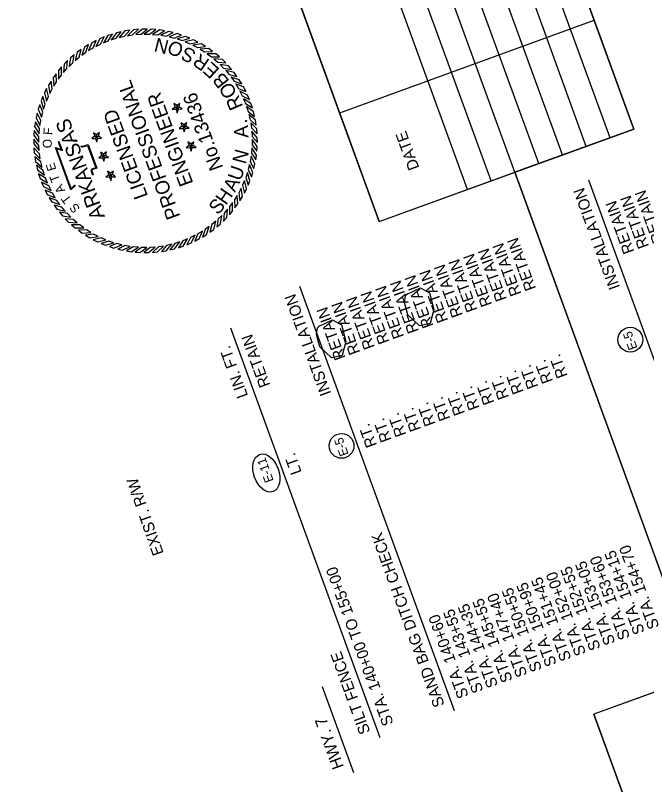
# Model space of a CAD drawing. Extents: x 986289 to 987754, y 1871116 to 1872971.
# Drawn here: x 986700.1 to 987036.8, y 1871784 to 1872194.5 of the extents above; entities that cross this region are included whole.
import ezdxf

# ---------------------------------------------------------------- set-up
doc = ezdxf.new("R2010")
doc.units = 0
for name, color, linetype in [('1', 7, 'Continuous'), ('44', 7, 'Continuous'), ('Default', 7, 'Continuous'), ('G-ANNO-SYMB', 7, 'Continuous'), ('NO PLOT', 7, 'Continuous'), ('R_Draft', 7, 'Continuous'), ('S_TREE', 7, 'Continuous')]:
    doc.layers.add(name, color=color, linetype=linetype)

msp = doc.modelspace()

# ---------------------------------------------------------------- linework, layer by layer
at = {"layer": '1'}
for p, q in [((987064.47, 1871841.86), (986966.59, 1872110.78)), ((987122.5, 1871862.99), (987008.75, 1871821.58)), ((987125.95, 1871499.59), (987008.75, 1871821.58))]:
    msp.add_line(p, q, dxfattribs=at)
for centre in [(987028.16, 1872021.45), (986874.09, 1871964.77)]:
    msp.add_circle(centre, 6.61, dxfattribs=at)
msp.add_ellipse((986833.97, 1871950.31), major_axis=(-3.6, 9.89), ratio=0.638788, dxfattribs=at)
at = {"layer": '44'}
for p, q in [((987088.39, 1871880.02), (987005.96, 1872106.5)), ((986934.32, 1871823.34), (986851.89, 1872049.82)), ((986894.7, 1871808.92), (986815.08, 1872027.68)), ((986880.63, 1871790.3), (986863.92, 1871836.2))]:
    msp.add_line(p, q, dxfattribs=at)
at = {"layer": 'Default'}
for p, q in [((987030.02, 1872133.87), (986884.66, 1872533.24)), ((987017.33, 1872129.25), (986871.97, 1872528.62)), ((987004.65, 1872124.63), (986859.29, 1872524)), ((986991.96, 1872120.02), (986846.6, 1872519.39)), ((986979.27, 1872115.4), (986833.92, 1872514.77)), ((986979.27, 1872115.4), (986833.92, 1872514.77)), ((986966.59, 1872110.78), (986821.23, 1872510.15)), ((986953.9, 1872106.17), (986808.54, 1872505.53)), ((986941.22, 1872101.55), (986795.86, 1872500.92)), ((986894.23, 1872084.45), (986748.87, 1872483.82)), ((986873.09, 1872142.53), (987008.88, 1872191.95)), ((986894.23, 1872084.45), (987030.02, 1872133.87))]:
    msp.add_line(p, q, dxfattribs=at)
at = {"layer": 'G-ANNO-SYMB'}
for points in [[(986756.46, 1872185.78), (986753.97, 1872185.17), (986751.25, 1872181.49), (986753.9, 1872182.32)], [(986761.07, 1872186.63), (986758.54, 1872186.21), (986755.54, 1872182.76), (986758.24, 1872183.37)], [(986765.73, 1872187.11), (986763.17, 1872186.89), (986759.91, 1872183.69), (986762.65, 1872184.09)], [(986770.41, 1872187.22), (986767.85, 1872187.21), (986764.34, 1872184.27), (986767.11, 1872184.45)], [(986775.09, 1872186.97), (986772.53, 1872187.15), (986768.81, 1872184.5), (986771.58, 1872184.46)], [(986779.73, 1872186.35), (986777.2, 1872186.73), (986773.28, 1872184.38), (986776.04, 1872184.13)], [(986784.31, 1872185.36), (986781.81, 1872185.95), (986777.72, 1872183.91), (986780.45, 1872183.44)], [(986788.8, 1872184.03), (986786.36, 1872184.8), (986782.12, 1872183.09), (986784.8, 1872182.41)], [(986743.23, 1872181.13), (986740.95, 1872179.95), (986739.17, 1872175.74), (986741.55, 1872177.16)], [(986747.51, 1872183.03), (986745.15, 1872182.03), (986743.04, 1872177.97), (986745.52, 1872179.2)], [(986751.93, 1872184.58), (986749.5, 1872183.77), (986747.08, 1872179.89), (986749.65, 1872180.92)], [(986793.17, 1872182.34), (986790.79, 1872183.3), (986786.43, 1872181.93), (986789.06, 1872181.04)], [(986797.39, 1872180.31), (986795.1, 1872181.46), (986790.65, 1872180.43), (986793.19, 1872179.34)], [(986739.11, 1872178.9), (986736.93, 1872177.55), (986735.48, 1872173.21), (986737.74, 1872174.81)], [(986801.45, 1872177.96), (986799.25, 1872179.29), (986794.73, 1872178.61), (986797.18, 1872177.33)], [(986805.3, 1872175.3), (986803.22, 1872176.8), (986798.66, 1872176.48), (986801, 1872175)], [(986731.45, 1872173.51), (986729.51, 1872171.83), (986728.76, 1872167.32), (986730.74, 1872169.26)], [(986735.18, 1872176.36), (986733.11, 1872174.84), (986732, 1872170.4), (986734.13, 1872172.17)], [(986808.94, 1872172.35), (986806.98, 1872174), (986802.4, 1872174.04), (986804.63, 1872172.38)], [(986727.97, 1872170.39), (986726.16, 1872168.56), (986725.77, 1872164), (986727.59, 1872166.09)], [(986812.33, 1872169.12), (986810.5, 1872170.92), (986805.95, 1872171.32), (986808.03, 1872169.49)], [(986815.46, 1872165.63), (986813.78, 1872167.57), (986809.27, 1872168.32), (986811.2, 1872166.34)], [(986724.74, 1872166.99), (986723.08, 1872165.03), (986723.04, 1872160.46), (986724.7, 1872162.68)], [(986818.3, 1872161.91), (986816.78, 1872163.97), (986812.34, 1872165.08), (986814.12, 1872162.95)], [(986721.78, 1872163.36), (986720.29, 1872161.27), (986720.61, 1872156.71), (986722.08, 1872159.06)], [(986820.84, 1872157.97), (986819.49, 1872160.15), (986815.15, 1872161.6), (986816.76, 1872159.34)], [(986719.12, 1872159.5), (986717.79, 1872157.31), (986718.47, 1872152.78), (986719.76, 1872155.24)], [(986823.07, 1872153.85), (986821.89, 1872156.13), (986817.68, 1872157.92), (986819.1, 1872155.54)], [(986716.77, 1872155.45), (986715.62, 1872153.16), (986716.65, 1872148.7), (986717.74, 1872151.25)], [(986824.97, 1872149.57), (986823.97, 1872151.93), (986819.92, 1872154.04), (986821.14, 1872151.56)], [(986714.74, 1872151.23), (986713.78, 1872148.85), (986715.15, 1872144.49), (986716.04, 1872147.12)], [(986826.52, 1872145.15), (986825.72, 1872147.58), (986821.84, 1872150.01), (986822.87, 1872147.43)], [(986713.06, 1872146.86), (986712.28, 1872144.41), (986713.99, 1872140.17), (986714.67, 1872142.86)], [(986786.39, 1872145.32), (986785.38, 1872145.61), (986783.82, 1872144.39), (986785.8, 1872144.46)], [(986786.39, 1872145.32), (986786.35, 1872146.36), (986784.71, 1872147.47), (986785.38, 1872145.61)], [(986786.39, 1872145.32), (986785.8, 1872144.46), (986786.48, 1872142.59), (986787.03, 1872144.5)], [(986786.39, 1872145.32), (986787.36, 1872145.68), (986787.91, 1872147.58), (986786.35, 1872146.36)], [(986786.39, 1872145.32), (986787.03, 1872144.5), (986789.01, 1872144.57), (986787.36, 1872145.68)], [(986827.73, 1872140.62), (986827.11, 1872143.11), (986823.44, 1872145.83), (986824.26, 1872143.19)], [(986711.72, 1872142.37), (986711.14, 1872139.87), (986713.18, 1872135.78), (986713.64, 1872138.51)], [(986828.57, 1872136.01), (986828.15, 1872138.55), (986824.7, 1872141.55), (986825.32, 1872138.84)], [(986710.74, 1872137.79), (986710.35, 1872135.25), (986712.71, 1872131.33), (986712.96, 1872134.09)], [(986790.12, 1872135.07), (986790.08, 1872136.11), (986788.44, 1872137.22), (986789.11, 1872135.36)], [(986790.12, 1872135.07), (986791.1, 1872135.42), (986791.64, 1872137.33), (986790.08, 1872136.11)], [(986829.05, 1872131.35), (986828.83, 1872133.91), (986825.63, 1872137.17), (986826.03, 1872134.43)], [(986710.11, 1872133.14), (986709.93, 1872130.59), (986712.59, 1872126.86), (986712.62, 1872129.63)], [(986743.46, 1872129.7), (986743.42, 1872130.74), (986741.78, 1872131.84), (986742.46, 1872129.98)], [(986743.46, 1872129.7), (986744.44, 1872130.05), (986744.98, 1872131.96), (986743.42, 1872130.74)], [(986790.12, 1872135.07), (986789.11, 1872135.36), (986787.55, 1872134.14), (986789.53, 1872134.2)], [(986790.12, 1872135.07), (986789.53, 1872134.2), (986790.21, 1872132.34), (986790.76, 1872134.25)], [(986790.12, 1872135.07), (986790.76, 1872134.25), (986792.74, 1872134.32), (986791.1, 1872135.42)], [(986829.17, 1872126.67), (986829.15, 1872129.24), (986826.21, 1872132.74), (986826.39, 1872129.97)], [(986709.86, 1872128.47), (986709.88, 1872125.9), (986712.82, 1872122.4), (986712.63, 1872125.16)], [(986743.46, 1872129.7), (986742.46, 1872129.98), (986740.9, 1872128.76), (986742.88, 1872128.83)], [(986743.46, 1872129.7), (986742.88, 1872128.83), (986743.55, 1872126.97), (986744.1, 1872128.87)], [(986743.46, 1872129.7), (986744.1, 1872128.87), (986746.08, 1872128.94), (986744.44, 1872130.05)], [(986828.91, 1872121.99), (986829.1, 1872124.55), (986826.44, 1872128.28), (986826.41, 1872125.5)], [(986709.97, 1872123.78), (986710.19, 1872121.23), (986713.4, 1872117.97), (986713, 1872120.71)], [(986793.85, 1872124.82), (986792.85, 1872125.1), (986791.28, 1872123.88), (986793.26, 1872123.95)], [(986793.85, 1872124.82), (986793.81, 1872125.86), (986792.17, 1872126.97), (986792.85, 1872125.1)], [(986793.85, 1872124.82), (986793.26, 1872123.95), (986793.94, 1872122.09), (986794.49, 1872124)], [(986793.85, 1872124.82), (986794.83, 1872125.17), (986795.37, 1872127.08), (986793.81, 1872125.86)], [(986793.85, 1872124.82), (986794.49, 1872124), (986796.47, 1872124.07), (986794.83, 1872125.17)], [(986828.29, 1872117.35), (986828.68, 1872119.89), (986826.32, 1872123.81), (986826.07, 1872121.05)], [(986710.45, 1872119.12), (986710.87, 1872116.59), (986714.32, 1872113.59), (986713.71, 1872116.3)], [(986747.19, 1872119.44), (986746.19, 1872119.73), (986744.63, 1872118.51), (986746.61, 1872118.58)], [(986747.19, 1872119.44), (986747.15, 1872120.49), (986745.51, 1872121.59), (986746.19, 1872119.73)], [(986747.19, 1872119.44), (986746.61, 1872118.58), (986747.28, 1872116.72), (986747.83, 1872118.62)], [(986747.19, 1872119.44), (986748.17, 1872119.8), (986748.71, 1872121.71), (986747.15, 1872120.49)], [(986747.19, 1872119.44), (986747.83, 1872118.62), (986749.81, 1872118.69), (986748.17, 1872119.8)], [(986827.31, 1872112.77), (986827.89, 1872115.27), (986825.85, 1872119.36), (986825.38, 1872116.63)], [(986825.97, 1872108.28), (986826.75, 1872110.73), (986825.03, 1872114.97), (986824.35, 1872112.28)], [(986711.3, 1872114.52), (986711.91, 1872112.03), (986715.59, 1872109.31), (986714.76, 1872111.95)], [(986750.92, 1872109.19), (986750.88, 1872110.23), (986749.24, 1872111.34), (986749.92, 1872109.48)], [(986750.92, 1872109.19), (986751.9, 1872109.55), (986752.45, 1872111.45), (986750.88, 1872110.23)], [(986712.5, 1872109.99), (986713.31, 1872107.55), (986717.19, 1872105.13), (986716.16, 1872107.7)], [(986750.92, 1872109.19), (986749.92, 1872109.48), (986748.36, 1872108.26), (986750.34, 1872108.33)], [(986750.92, 1872109.19), (986750.34, 1872108.33), (986751.02, 1872106.47), (986751.56, 1872108.37)], [(986750.92, 1872109.19), (986751.56, 1872108.37), (986753.54, 1872108.44), (986751.9, 1872109.55)], [(986824.28, 1872103.91), (986825.25, 1872106.29), (986823.87, 1872110.65), (986822.98, 1872108.02)], [(986714.06, 1872105.57), (986715.05, 1872103.21), (986719.11, 1872101.1), (986717.88, 1872103.58)], [(986822.26, 1872099.69), (986823.41, 1872101.98), (986822.38, 1872106.44), (986821.29, 1872103.89)], [(986715.95, 1872101.29), (986717.13, 1872099.01), (986721.34, 1872097.22), (986719.92, 1872099.6)], [(986819.91, 1872095.64), (986821.23, 1872097.83), (986820.56, 1872102.35), (986819.27, 1872099.9)], [(986718.18, 1872097.17), (986719.54, 1872094.99), (986723.87, 1872093.54), (986722.27, 1872095.8)], [(986814.29, 1872088.15), (986815.94, 1872090.11), (986815.98, 1872094.68), (986814.33, 1872092.46)], [(986817.25, 1872091.78), (986818.74, 1872093.87), (986818.42, 1872098.43), (986816.94, 1872096.08)], [(986720.73, 1872093.23), (986722.25, 1872091.17), (986726.68, 1872090.06), (986724.91, 1872092.19)], [(986811.06, 1872084.75), (986812.86, 1872086.58), (986813.26, 1872091.13), (986811.43, 1872089.05)], [(986723.57, 1872089.51), (986725.25, 1872087.57), (986729.76, 1872086.82), (986727.82, 1872088.8)], [(986807.57, 1872081.63), (986809.51, 1872083.3), (986810.27, 1872087.81), (986808.28, 1872085.88)], [(986726.7, 1872086.02), (986728.52, 1872084.22), (986733.08, 1872083.82), (986730.99, 1872085.65)], [(986730.09, 1872082.79), (986732.05, 1872081.14), (986736.62, 1872081.1), (986734.4, 1872082.75)], [(986803.85, 1872078.78), (986805.92, 1872080.3), (986807.02, 1872084.74), (986804.89, 1872082.97)], [(986733.72, 1872079.84), (986735.81, 1872078.34), (986740.37, 1872078.66), (986738.02, 1872080.14)], [(986795.79, 1872074.01), (986798.07, 1872075.19), (986799.86, 1872079.4), (986797.48, 1872077.98)], [(986799.92, 1872076.24), (986802.09, 1872077.59), (986803.55, 1872081.93), (986801.28, 1872080.33)], [(986737.58, 1872077.18), (986739.78, 1872075.85), (986744.3, 1872076.53), (986741.84, 1872077.81)], [(986741.63, 1872074.83), (986743.92, 1872073.68), (986748.38, 1872074.7), (986745.83, 1872075.8)], [(986745.86, 1872072.8), (986748.23, 1872071.83), (986752.59, 1872073.21), (986749.97, 1872074.1)], [(986787.09, 1872070.56), (986789.53, 1872071.37), (986791.95, 1872075.25), (986789.38, 1872074.22)], [(986791.51, 1872072.11), (986793.88, 1872073.11), (986795.99, 1872077.17), (986793.5, 1872075.94)], [(986750.23, 1872071.11), (986752.67, 1872070.34), (986756.91, 1872072.05), (986754.22, 1872072.73)], [(986754.71, 1872069.77), (986757.21, 1872069.19), (986761.31, 1872071.23), (986758.57, 1872071.7)], [(986759.29, 1872068.79), (986761.83, 1872068.41), (986765.75, 1872070.76), (986762.99, 1872071.01)], [(986763.94, 1872068.17), (986766.5, 1872067.99), (986770.22, 1872070.64), (986767.45, 1872070.67)], [(986768.62, 1872067.92), (986771.18, 1872067.93), (986774.68, 1872070.87), (986771.92, 1872070.69)], [(986773.3, 1872068.03), (986775.85, 1872068.25), (986779.12, 1872071.45), (986776.37, 1872071.05)], [(986777.96, 1872068.51), (986780.49, 1872068.93), (986783.49, 1872072.38), (986780.79, 1872071.76)], [(986782.57, 1872069.36), (986785.06, 1872069.97), (986787.78, 1872073.65), (986785.13, 1872072.82)]]:
    msp.add_lwpolyline(points, close=True, dxfattribs=at)
for points in [[(986731.82, 1872104.05), (986729.89, 1872102.13), (986722.12, 1872123.44), (986725.2, 1872122.41), (986724.33, 1872124.69), (986723.86, 1872125.94), (986723.54, 1872127.25)], [(986732.09, 1872103.78), (986729.74, 1872101.44), (986721.5, 1872124.05), (986724.56, 1872123.02), (986723.98, 1872124.55), (986723.49, 1872125.83), (986723.17, 1872127.16)], [(986734.92, 1872124.64), (986735.48, 1872124.31), (986736.14, 1872124.36), (986737.41, 1872124.67), (986738.64, 1872125.12), (986742.97, 1872113.21), (986741.22, 1872112.58), (986740.48, 1872112.31), (986740.53, 1872111.4), (986741.13, 1872109.75), (986740.89, 1872109.41)], [(986735.11, 1872124.97), (986735.57, 1872124.7), (986736.08, 1872124.74), (986737.3, 1872125.04), (986738.86, 1872125.61), (986743.46, 1872112.99), (986741.35, 1872112.22), (986740.88, 1872112.05), (986740.91, 1872111.48), (986741.56, 1872109.68), (986741.19, 1872109.19)]]:
    msp.add_lwpolyline(points, dxfattribs=at)
at = {"layer": 'NO PLOT'}
for points in [[(987753.66, 1871472.09), (987208.01, 1872971.24), (986718.28, 1872792.99), (986821.23, 1872510.15), (986884.66, 1872533.24), (987030.02, 1872133.87), (986966.59, 1872110.78), (987064.47, 1871841.86), (987122.5, 1871862.99), (987239.7, 1871540.99), (987181.66, 1871519.87), (987263.93, 1871293.85)], [(987753.66, 1871472.09), (987208.01, 1872971.24), (986718.28, 1872792.99), (986821.23, 1872510.15), (986884.66, 1872533.24), (987030.02, 1872133.87), (986966.59, 1872110.78), (987064.47, 1871841.86), (987122.5, 1871862.99), (987239.7, 1871540.99), (987181.66, 1871519.87), (987263.93, 1871293.85)], [(987753.66, 1871472.09), (987208.01, 1872971.24), (986718.28, 1872792.99), (986821.23, 1872510.15), (986884.66, 1872533.24), (987030.02, 1872133.87), (986966.59, 1872110.78), (987064.47, 1871841.86), (987122.5, 1871862.99), (987239.7, 1871540.99), (987181.66, 1871519.87), (987263.93, 1871293.85)], [(987753.66, 1871472.09), (987208.01, 1872971.24), (986718.28, 1872792.99), (986821.23, 1872510.15), (986884.66, 1872533.24), (987030.02, 1872133.87), (986966.59, 1872110.78), (987064.47, 1871841.86), (987122.5, 1871862.99), (987239.7, 1871540.99), (987181.66, 1871519.87), (987263.93, 1871293.85)], [(987753.66, 1871472.09), (987208.01, 1872971.24), (986718.28, 1872792.99), (986821.23, 1872510.15), (986884.66, 1872533.24), (987030.02, 1872133.87), (986966.59, 1872110.78), (987064.47, 1871841.86), (987122.5, 1871862.99), (987239.7, 1871540.99), (987181.66, 1871519.87), (987263.93, 1871293.85)], [(987753.66, 1871472.09), (987208.01, 1872971.24), (986718.28, 1872792.99), (986821.23, 1872510.15), (986884.66, 1872533.24), (987030.02, 1872133.87), (986966.59, 1872110.78), (987064.47, 1871841.86), (987122.5, 1871862.99), (987239.7, 1871540.99), (987181.66, 1871519.87), (987263.93, 1871293.85)], [(987753.66, 1871472.09), (987208.01, 1872971.24), (986718.28, 1872792.99), (986821.23, 1872510.15), (986884.66, 1872533.24), (987030.02, 1872133.87), (986966.59, 1872110.78), (987064.47, 1871841.86), (987122.5, 1871862.99), (987239.7, 1871540.99), (987181.66, 1871519.87), (987263.93, 1871293.85)], [(986774.2, 1871115.6), (986369.23, 1872228.25), (986415.65, 1872245.15), (986348.68, 1872429.14), (986362.4, 1872434.13), (986288.69, 1872636.64), (986718.28, 1872792.99), (986821.23, 1872510.15), (986748.87, 1872483.82), (986894.23, 1872084.45), (986966.59, 1872110.78), (987064.47, 1871841.86), (987008.75, 1871821.58), (987125.95, 1871499.59), (987181.66, 1871519.87), (987263.93, 1871293.85)], [(986774.2, 1871115.6), (986369.23, 1872228.25), (986415.65, 1872245.15), (986348.68, 1872429.14), (986362.4, 1872434.13), (986288.69, 1872636.64), (986718.28, 1872792.99), (986821.23, 1872510.15), (986748.87, 1872483.82), (986894.23, 1872084.45), (986966.59, 1872110.78), (987064.47, 1871841.86), (987008.75, 1871821.58), (987125.95, 1871499.59), (987181.66, 1871519.87), (987263.93, 1871293.85)], [(986774.2, 1871115.6), (986369.23, 1872228.25), (986415.65, 1872245.15), (986348.68, 1872429.14), (986362.4, 1872434.13), (986288.69, 1872636.64), (986718.28, 1872792.99), (986821.23, 1872510.15), (986748.87, 1872483.82), (986894.23, 1872084.45), (986966.59, 1872110.78), (987064.47, 1871841.86), (987008.75, 1871821.58), (987125.95, 1871499.59), (987181.66, 1871519.87), (987263.93, 1871293.85)], [(986774.2, 1871115.6), (986369.23, 1872228.25), (986415.65, 1872245.15), (986348.68, 1872429.14), (986362.4, 1872434.13), (986288.69, 1872636.64), (986718.28, 1872792.99), (986821.23, 1872510.15), (986748.87, 1872483.82), (986894.23, 1872084.45), (986966.59, 1872110.78), (987064.47, 1871841.86), (987008.75, 1871821.58), (987125.95, 1871499.59), (987181.66, 1871519.87), (987263.93, 1871293.85)], [(986774.2, 1871115.6), (986369.23, 1872228.25), (986415.65, 1872245.15), (986348.68, 1872429.14), (986362.4, 1872434.13), (986288.69, 1872636.64), (986718.28, 1872792.99), (986821.23, 1872510.15), (986748.87, 1872483.82), (986894.23, 1872084.45), (986966.59, 1872110.78), (987064.47, 1871841.86), (987008.75, 1871821.58), (987125.95, 1871499.59), (987181.66, 1871519.87), (987263.93, 1871293.85)], [(986774.2, 1871115.6), (986369.23, 1872228.25), (986415.65, 1872245.15), (986348.68, 1872429.14), (986362.4, 1872434.13), (986288.69, 1872636.64), (986718.28, 1872792.99), (986821.23, 1872510.15), (986748.87, 1872483.82), (986894.23, 1872084.45), (986966.59, 1872110.78), (987064.47, 1871841.86), (987008.75, 1871821.58), (987125.95, 1871499.59), (987181.66, 1871519.87), (987263.93, 1871293.85)]]:
    msp.add_lwpolyline(points, close=True, dxfattribs=at)
at = {"layer": 'S_TREE'}
for points in [[(986908.79, 1872045.63), (986916.26, 1872049.12), (986921.09, 1872046.38), (986923.24, 1872037.55), (986921.31, 1872030.17), (986915.6, 1872028.9), (986909.52, 1872034.78), (986907.67, 1872041.23), (986908.28, 1872044.88), (986909.47, 1872046.1)], [(986861.85, 1872028.54), (986869.32, 1872032.03), (986874.15, 1872029.3), (986876.3, 1872020.47), (986874.37, 1872013.09), (986868.66, 1872011.81), (986862.58, 1872017.7), (986860.73, 1872024.14), (986861.34, 1872027.8), (986862.53, 1872029.02)]]:
    msp.add_lwpolyline(points, dxfattribs=at)

# ---------------------------------------------------------------- texts
at = {"layer": '1'}
for s, p in [('E-5 ', (987032, 1872017)), ('E-5 ', (986877.93, 1871960.32)), ('E-11', (986837.96, 1871946.23))]:
    msp.add_text(s, height=4.8, rotation=110, dxfattribs=at).set_placement(p)
at = {"layer": '44'}
for s, height, p in [('INSTALLATION', 6, (987022.74, 1872049.43)), ('RETAIN', 6, (987046.02, 1872074.2)), ('RETAIN', 6, (987030.36, 1872068.5)), ('RETAIN', 6, (987038.19, 1872071.35)), ('RETAIN', 6, (986977.96, 1872048.83)), ('RETAIN', 6, (986962.34, 1872043.14)), ('RETAIN', 6, (986970.13, 1872045.98)), ('RETAIN', 6, (986954.51, 1872040.29)), ('RETAIN', 6, (986938.89, 1872034.6)), ('RETAIN', 6, (986946.68, 1872037.44)), ('RETAIN', 6, (986931.06, 1872031.75)), ('RETAIN', 6, (986923.2, 1872028.89)), ('RETAIN', 6, (986907.57, 1872023.21)), ('RETAIN', 6, (986915.4, 1872026.06)), ('INSTALLATION', 6, (986868.67, 1871992.75)), ('RETAIN', 6, (986899.74, 1872020.36)), ('RETAIN', 6, (986884.12, 1872014.67)), ('RETAIN', 6, (986891.95, 1872017.52)), ('RETAIN', 6, (986876.29, 1872011.82)), ('RETAIN', 6, (986836.2, 1871997.23)), ('LIN. FT.', 6, (986824.26, 1871991.5)), ('RT.', 6, (986994.81, 1872002.18)), ('RT.', 6, (986986.98, 1871999.33)), ('RT.', 6, (986971.32, 1871993.63)), ('RT.', 6, (986979.15, 1871996.48)), ('RT.', 6, (986963.49, 1871990.78)), ('RT.', 6, (986947.87, 1871985.1)), ('RT.', 6, (986955.7, 1871987.95)), ('RT.', 6, (986940.04, 1871982.25)), ('RT.', 6, (986924.38, 1871976.55)), ('RT.', 6, (986932.21, 1871979.4)), ('RT.', 6, (986916.55, 1871973.7)), ('RT.', 6, (986908.76, 1871970.86)), ('RT.', 6, (986893.1, 1871965.16)), ('RT.', 6, (986900.93, 1871968.01)), ('LT.', 6, (986852.95, 1871950.7)), ('SAND BAG DITCH CHECK', 6, (986929.15, 1871826.56)), ('STA. 154+70', 6, (987043.71, 1871868.26)), ('STA. 153+60', 6, (987028.05, 1871862.56)), ('STA. 154+15', 6, (987035.88, 1871865.41)), ('STA. 153+05', 6, (987020.22, 1871859.71)), ('STA. 140+00 TO 155+00', 6, (986901.9, 1871816.65)), ('STA. 152+00', 6, (987004.6, 1871854.02)), ('STA. 152+55', 6, (987012.39, 1871856.86)), ('STA. 151+45', 6, (986996.77, 1871851.17)), ('STA. 150+95', 6, (986988.94, 1871848.32)), ('STA. 147+40', 6, (986973.28, 1871842.63)), ('STA. 150+55', 6, (986981.11, 1871845.48)), ('STA. 145+55', 6, (986965.45, 1871839.78)), ('STA. 143+55', 6, (986949.83, 1871834.09)), ('STA. 144+35', 6, (986957.66, 1871836.94)), ('STA. 140+60', 6, (986942, 1871831.24)), ('SILT FENCE      ', 6, (986889.53, 1871812.14)), ('HWY. 7', 6.25, (986875.42, 1871793.56))]:
    msp.add_text(s, height=height, rotation=110, dxfattribs=at).set_placement(p)
at = {"layer": 'Default'}
msp.add_text('DATE', height=6, rotation=110, dxfattribs=at).set_placement((986915.7, 1872113.17))
at = {"layer": 'G-ANNO-SYMB'}
for s, height, rotation, p in [('N', 7.5, 166.1007, (986782.47, 1872180.96)), ('O', 7.5, 154.7757, (986790.6, 1872178.38)), ('S', 7.5, 153.4878, (986797.03, 1872175.23)), ('R', 7.5, 145.6597, (986804.18, 1872170.5)), ('E', 7.5, 137.8315, (986809.47, 1872165.68)), ('PROFESSIONAL', 7.5, 110, (986788.18, 1872087.24)), ('B', 7.5, 128.885, (986814.61, 1872159.49)), ('O', 7.5, 121.4296, (986818.67, 1872152.97)), ('ENGINEER', 7.5, 110, (986795.08, 1872104.95)), ('No.13436', 7.47, 110, (986811.07, 1872113.29)), ('R', 7.5, 113.2287, (986821.75, 1872145.92)), ('LICENSED', 7.5, 110, (986770.9, 1872098.05)), ('ARKANSAS', 7.747, 110, (986747.96, 1872087.14)), ('A', 7.5, 93.0991, (986824.47, 1872129.28)), ('.', 7.5, 101.3, (986824.01, 1872136.95)), ('F', 4.75, 85.3628, (986719.72, 1872130.56)), ('O', 4.75, 91.2218, (986719.56, 1872123.69)), ('N', 7.5, 74.9326, (986822.9, 1872114.79)), ('E', 4.75, 106.672, (986721.97, 1872112.3)), ('U', 7.5, 70.9026, (986820.24, 1872105.78)), ('T', 4.75, 111.4789, (986723.92, 1872106.55)), ('A', 4.75, 118.6788, (986726.9, 1872101.11)), ('A', 7.5, 63.4472, (986817.24, 1872099.72)), ('H', 7.5, 55.619, (986812.44, 1872092.9)), ('T', 4.75, 126.9015, (986730.29, 1872096.21)), ('S', 7.5, 48.1636, (986808.08, 1872087.68)), ('S', 4.75, 129.7726, (986734.9, 1872091.46))]:
    msp.add_text(s, height=height, rotation=rotation, dxfattribs=at).set_placement(p)
at = {"layer": 'R_Draft'}
msp.add_text('EXIST. R/W', height=6, rotation=109.2927, dxfattribs=at).set_placement((986779.28, 1871907.51))

doc.saveas('drawing.dxf')
